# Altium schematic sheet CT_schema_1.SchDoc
size 656 x 463 mm
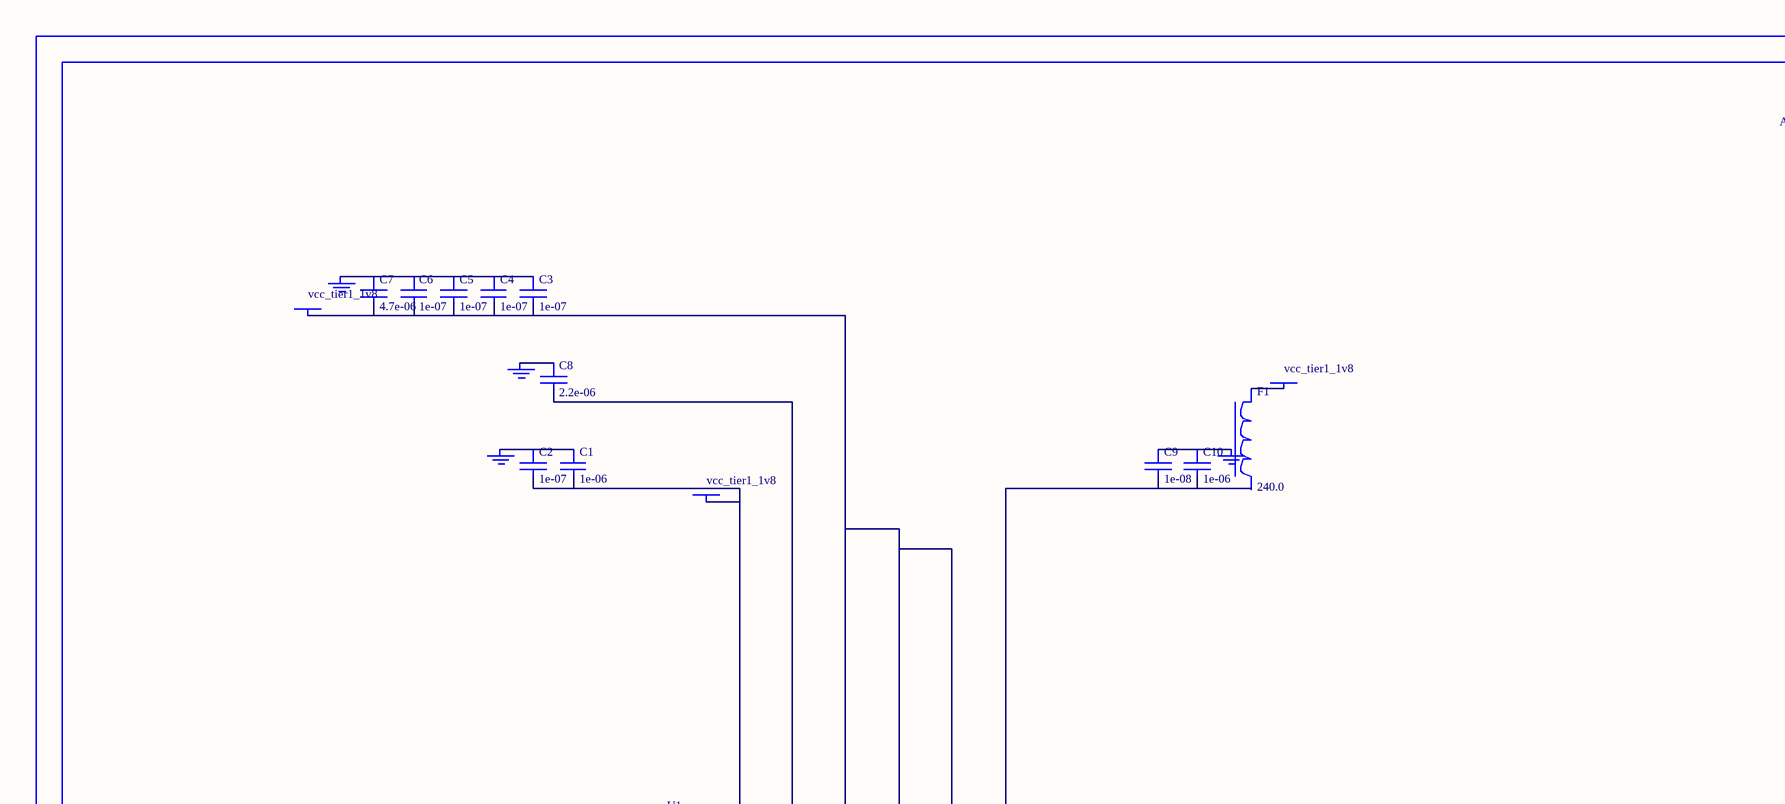
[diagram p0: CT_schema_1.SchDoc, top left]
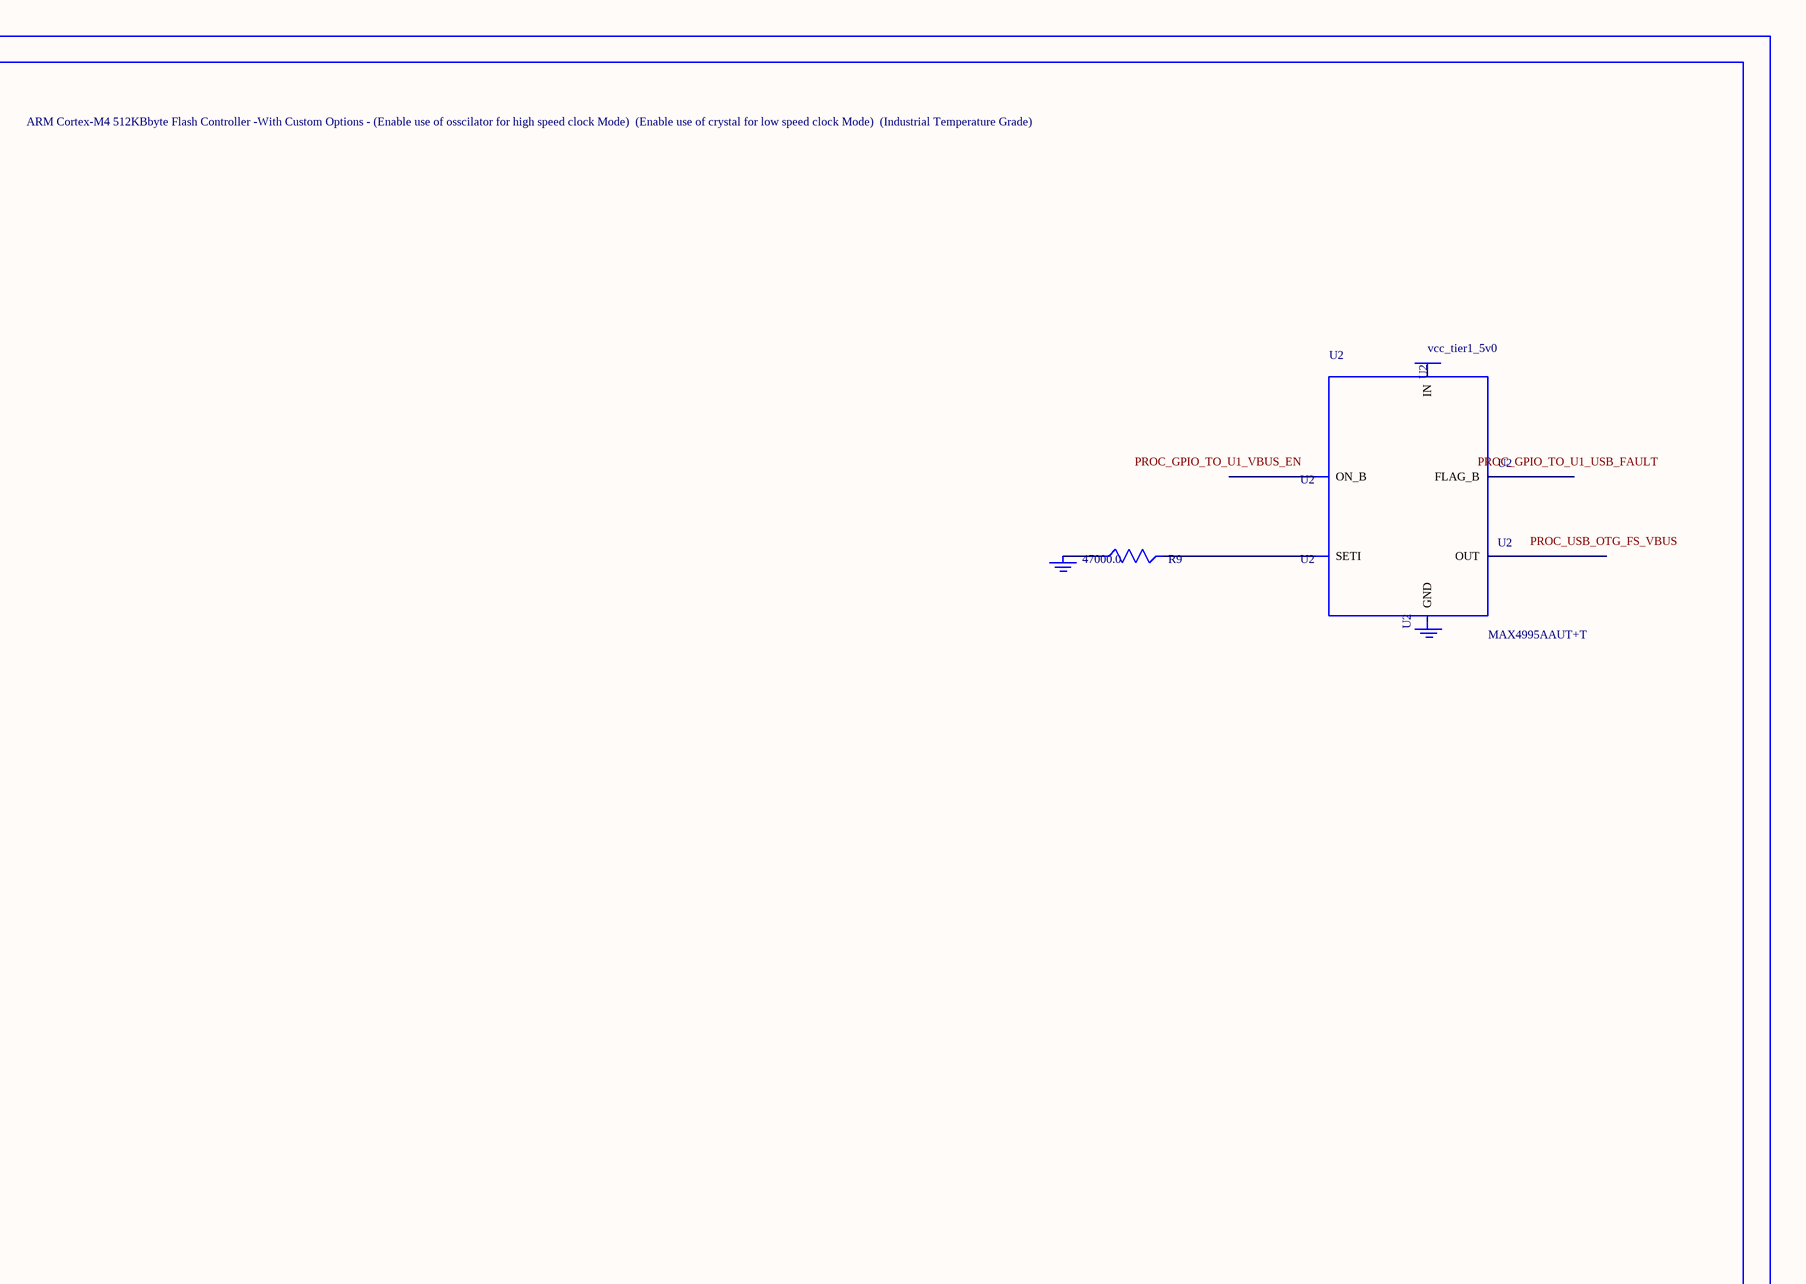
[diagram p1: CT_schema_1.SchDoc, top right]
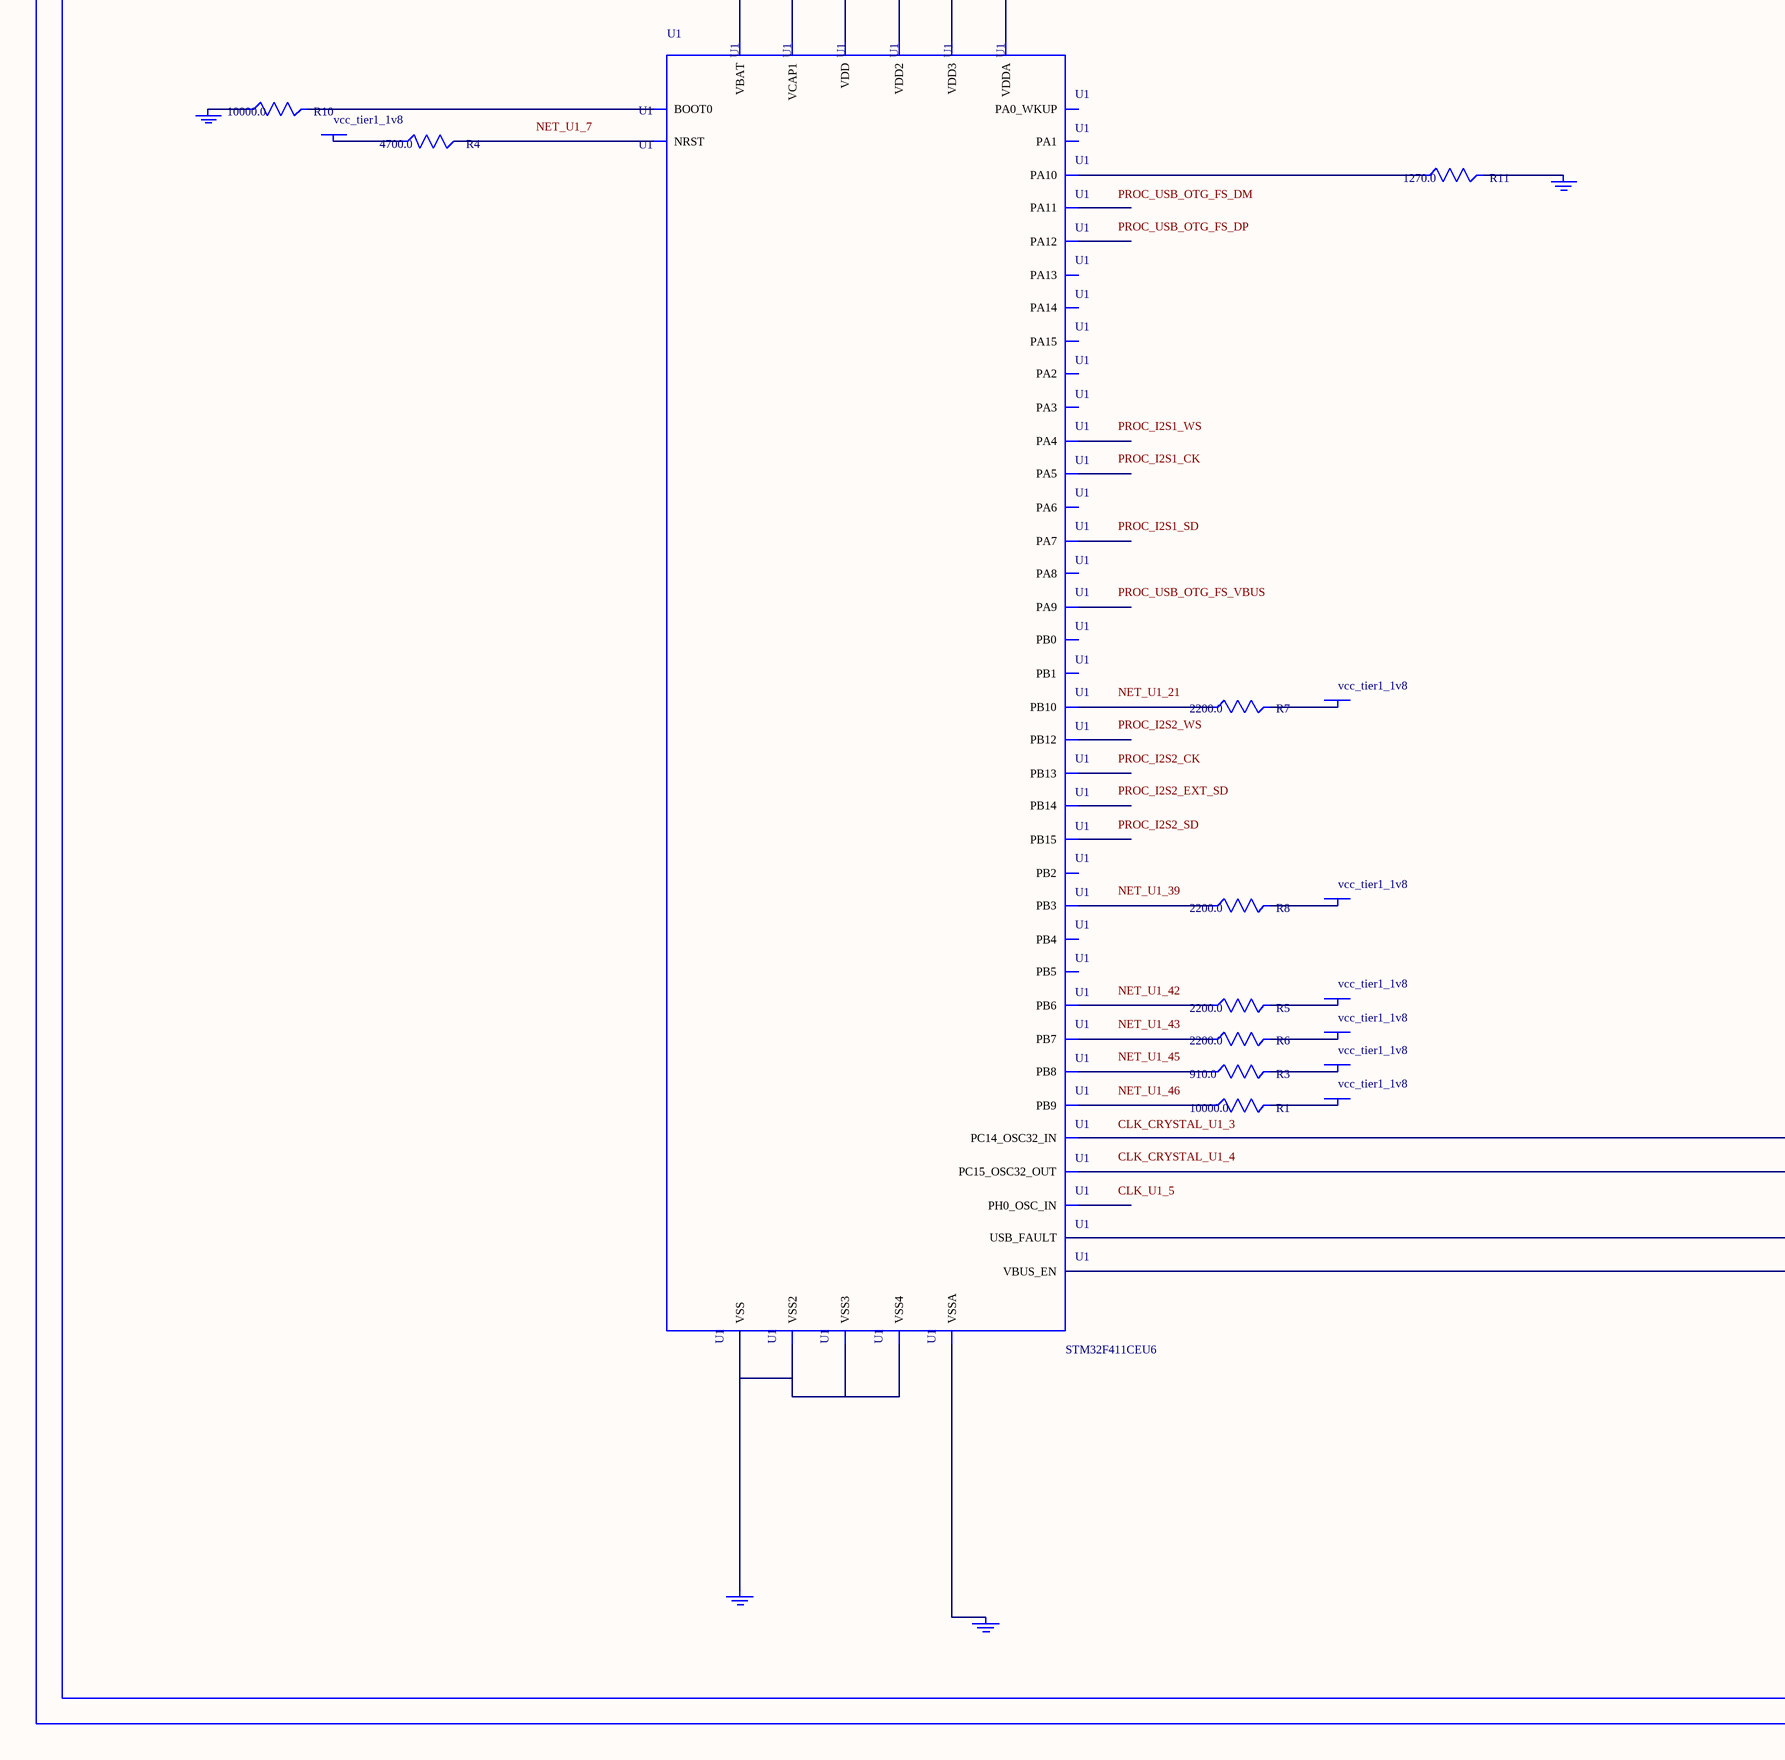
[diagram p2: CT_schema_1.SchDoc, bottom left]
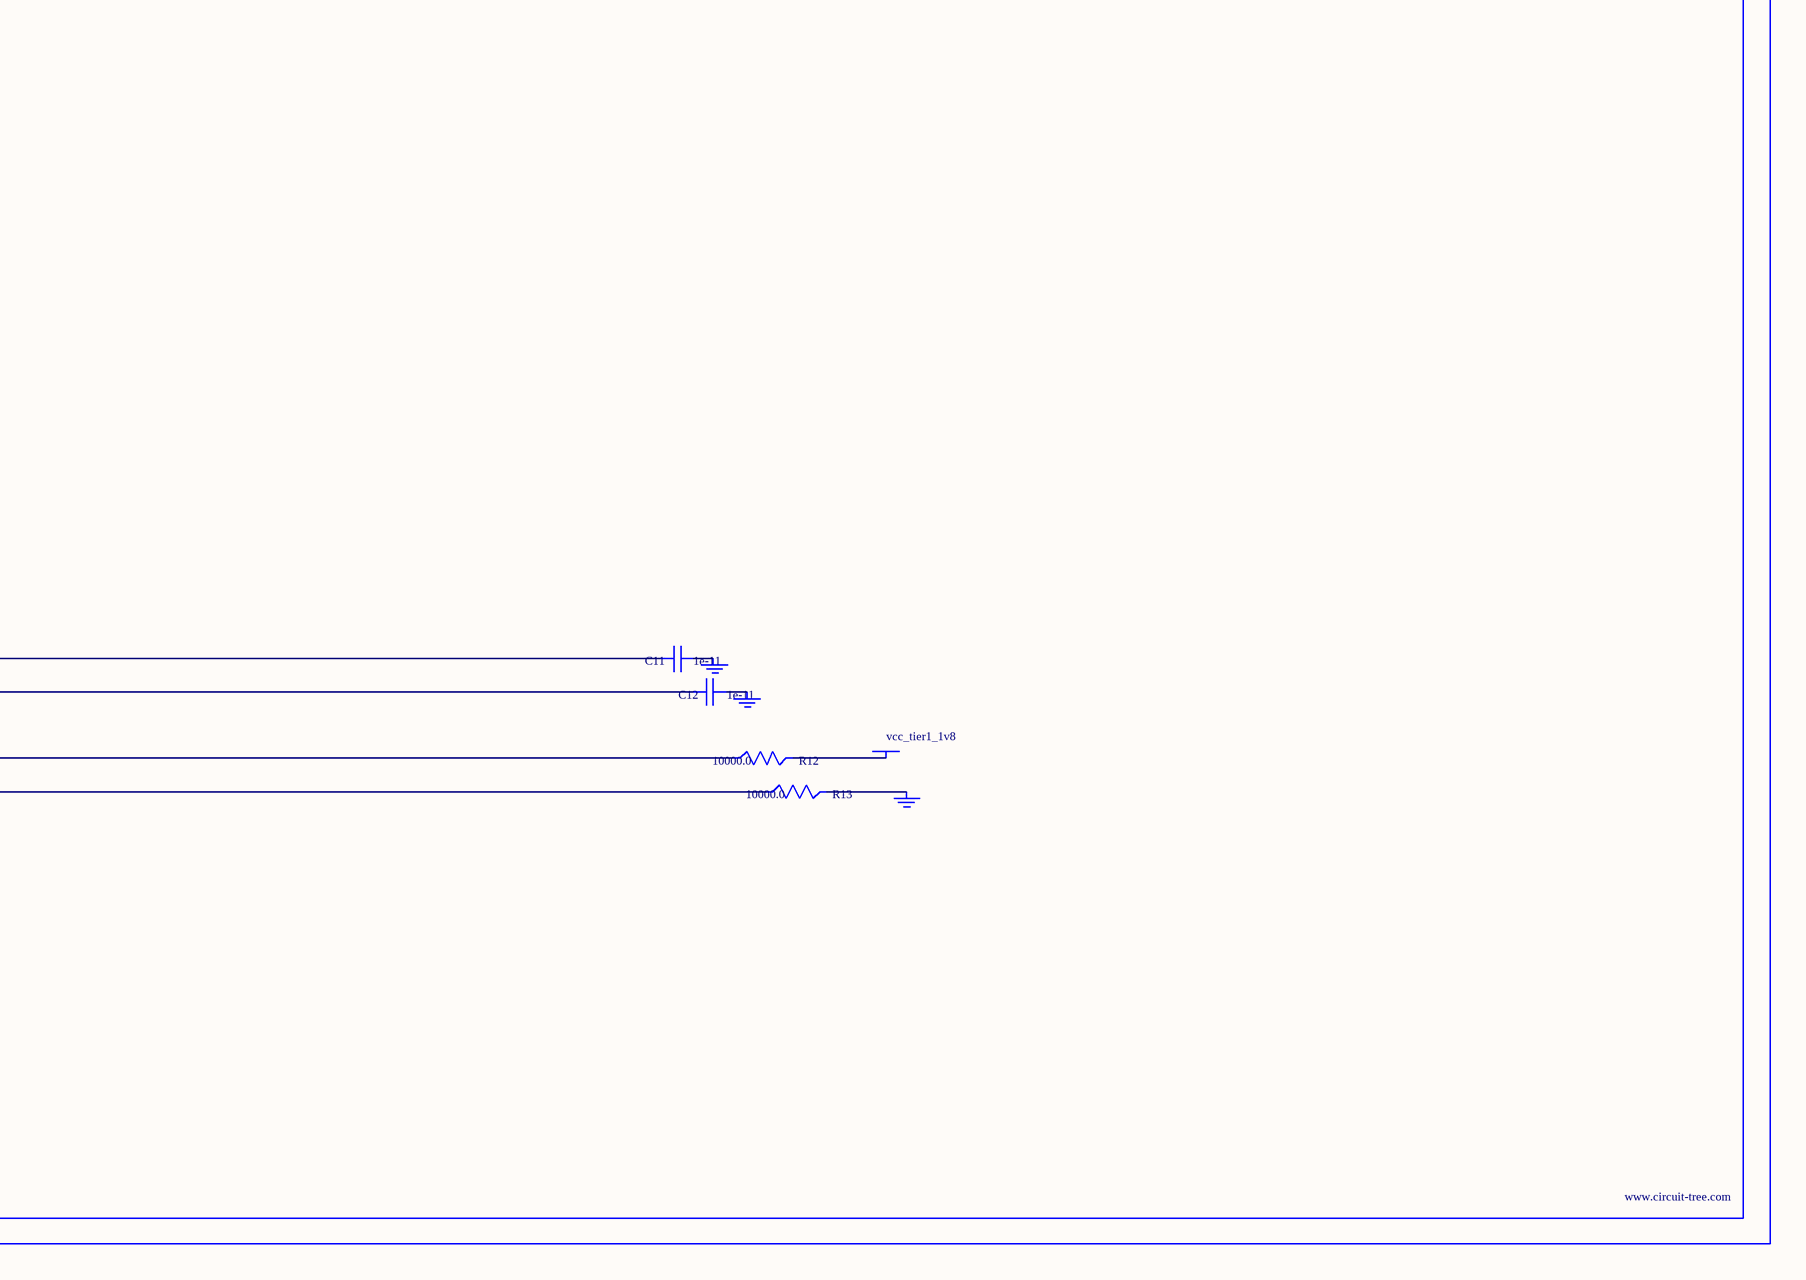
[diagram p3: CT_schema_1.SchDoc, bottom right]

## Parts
BORDER0  (no value)
C1  1e-06  [C0603]
C2  1e-07  [C0603]
C3  1e-07  [C0603]
C4  1e-07  [C0603]
C5  1e-07  [C0603]
C6  1e-07  [C0603]
C7  4.7e-06  [C0603]
C8  2.2e-06  [C0603]
C9  1e-08  [C0603]
C10  1e-06  [C0603]
C11  1e-11  [C0402]
C12  1e-11  [C0402]
F1  240.0  [L0603]
GND_INSTANCE_0_0  (no value)
GND_INSTANCE_0_1  (no value)
GND_INSTANCE_0_2  (no value)
GND_INSTANCE_0_3  (no value)
GND_INSTANCE_0_4  (no value)
GND_INSTANCE_0_5  (no value)
GND_INSTANCE_0_6  (no value)
GND_INSTANCE_0_7  (no value)
GND_INSTANCE_0_8  (no value)
GND_INSTANCE_0_9  (no value)
GND_INSTANCE_0_10  (no value)
GND_INSTANCE_0_11  (no value)
GND_INSTANCE_0_12  (no value)
POWER_INSTANCE_0_0  vcc_tier1_1v8
POWER_INSTANCE_0_1  vcc_tier1_1v8
POWER_INSTANCE_0_2  vcc_tier1_1v8
POWER_INSTANCE_0_3  vcc_tier1_1v8
POWER_INSTANCE_0_4  vcc_tier1_1v8
POWER_INSTANCE_0_5  vcc_tier1_1v8
POWER_INSTANCE_0_6  vcc_tier1_1v8
POWER_INSTANCE_0_7  vcc_tier1_1v8
POWER_INSTANCE_0_8  vcc_tier1_1v8
POWER_INSTANCE_0_9  vcc_tier1_1v8
POWER_INSTANCE_0_10  vcc_tier1_1v8
POWER_INSTANCE_0_11  vcc_tier1_5v0
R1  10000.0  [R0603]
R3  910.0  [R0603]
R4  4700.0  [R0603]
R5  2200.0  [R0603]
R6  2200.0  [R0603]
R7  2200.0  [R0603]
R8  2200.0  [R0603]
R9  47000.0  [R0603]
R10  10000.0  [R0603]
R11  1270.0  [R0603]
R12  10000.0  [R0603]
R13  10000.0  [R0603]
U1  STM32F411CEU6  [UFQFPN48]
U2  MAX4995AAUT+T  [SOT-23-6]

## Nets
NetC1_1: C1.1 C2.1 GND_INSTANCE_0_0.0(GND)
NetC1_2: C1.2 C2.2 POWER_INSTANCE_0_0.0(PWR) U1.1(VBAT)
NetC3_1: C3.1 C4.1 C5.1 C6.1 C7.1 GND_INSTANCE_0_7.0(GND)
NetC3_2: C3.2 C4.2 C5.2 C6.2 C7.2 POWER_INSTANCE_0_3.0(PWR) U1.24(VDD) U1.36(VDD2) U1.48(VDD3)
NetC8_1: C8.1 GND_INSTANCE_0_6.0(GND)
NetC8_2: C8.2 U1.22(VCAP1)
NetC9_1: C9.1 C10.1 GND_INSTANCE_0_5.0(GND)
NetC9_2: C9.2 C10.2 U1.9(VDDA)
NetC11_1: C11.1 GND_INSTANCE_0_2.0(GND)
NetC11_2: C11.2 U1.3(PC14_OSC32_IN)
NetC12_1: C12.1 GND_INSTANCE_0_3.0(GND)
NetC12_2: C12.2 U1.4(PC15_OSC32_OUT)
NetF1_1: F1.1 POWER_INSTANCE_0_2.0(PWR)
NetGND_INSTANCE_0_1_0: GND_INSTANCE_0_1.0(GND) R13.2
NetGND_INSTANCE_0_4_0: GND_INSTANCE_0_4.0(GND) U1.8(VSSA)
NetGND_INSTANCE_0_8_0: GND_INSTANCE_0_8.0(GND) R11.2
NetGND_INSTANCE_0_9_0: GND_INSTANCE_0_9.0(GND) R10.1
NetGND_INSTANCE_0_10_0: GND_INSTANCE_0_10.0(GND) U1.23(VSS) U1.35(VSS2) U1.47(VSS3) U1.49(VSS4)
NetGND_INSTANCE_0_11_0: GND_INSTANCE_0_11.0(GND) R9.1
NetPOWER_INSTANCE_0_1_0: POWER_INSTANCE_0_1.0(PWR) R12.2
NetPOWER_INSTANCE_0_4_0: POWER_INSTANCE_0_4.0(PWR) R4.1
NetPOWER_INSTANCE_0_5_0: POWER_INSTANCE_0_5.0(PWR) R7.2
NetPOWER_INSTANCE_0_6_0: POWER_INSTANCE_0_6.0(PWR) R8.2
NetPOWER_INSTANCE_0_7_0: POWER_INSTANCE_0_7.0(PWR) R5.2
NetPOWER_INSTANCE_0_8_0: POWER_INSTANCE_0_8.0(PWR) R6.2
NetPOWER_INSTANCE_0_9_0: POWER_INSTANCE_0_9.0(PWR) R3.2
NetPOWER_INSTANCE_0_10_0: POWER_INSTANCE_0_10.0(PWR) R1.2
NetR1_1: R1.1 U1.46(PB9)
NetR3_1: R3.1 U1.45(PB8)
NetR4_2: R4.2 U1.7(NRST)
NetR5_1: R5.1 U1.42(PB6)
NetR6_1: R6.1 U1.43(PB7)
NetR7_1: R7.1 U1.21(PB10)
NetR8_1: R8.1 U1.39(PB3)
NetR9_2: R9.2 U2.3(SETI)
NetR10_2: R10.2 U1.44(BOOT0)
NetR11_1: R11.1 U1.31(PA10)
NetR12_1: R12.1 U1.6(USB_FAULT)
NetR13_1: R13.1 U1.2(VBUS_EN)

Not connected (* = marked no-connect by the designer): F1 2; GND_INSTANCE_0_12 0(GND); POWER_INSTANCE_0_11 0(PWR); U1 5(PH0_OSC_IN) 10(PA0_WKUP) 11(PA1) 12(PA2) 13(PA3) 14(PA4) 15(PA5) 16(PA6) 17(PA7) 18(PB0) 19(PB1) 20(PB2) 25(PB12) 26(PB13) 27(PB14) 28(PB15) 29(PA8) 30(PA9) 32(PA11) 33(PA12) 34(PA13) 37(PA14) 38(PA15) 40(PB4) 41(PB5); U2 1(OUT) 2(GND) 4(ON_B) 5(IN) 6(FLAG_B)

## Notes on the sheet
- Labels drawn without touching a wire or pin: CLK_CRYSTAL_U1_3, CLK_CRYSTAL_U1_4, CLK_U1_5, NET_U1_7, NET_U1_21, NET_U1_39, NET_U1_42, NET_U1_43, NET_U1_45, NET_U1_46, PROC_GPIO_TO_U1_USB_FAULT, PROC_GPIO_TO_U1_VBUS_EN, PROC_I2S1_CK, PROC_I2S1_SD, PROC_I2S1_WS, PROC_I2S2_CK, PROC_I2S2_EXT_SD, PROC_I2S2_SD, PROC_I2S2_WS, PROC_USB_OTG_FS_DM, PROC_USB_OTG_FS_DP, PROC_USB_OTG_FS_VBUS

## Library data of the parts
BORDER0 = BORDER_PAGE0
C1 C10 = C0603C105K3RACTU
C2-C6 = 06035C104K4Z2A
C7 = GRM188R6YA475KE15D
C8 = C0603C225K8RACTU
C9 = 06035C103K4Z2A
C11 C12 = C0402C100K3GACTU
F1 = Z0603C241ASMST
GND_INSTANCE_0_0-GND_INSTANCE_0_12 = GND
POWER_INSTANCE_0_0-POWER_INSTANCE_0_11 = PWR
R1 R10 R12 R13 = RC0603JR-0710KL
R3 = RC0603JR-07910RL
R4 = RC0603JR-074K7L
R5-R8 = RC0603JR-072K2L
R9 = RC0603JR-0747KL
R11 = RC0603FR-071K27L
